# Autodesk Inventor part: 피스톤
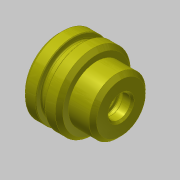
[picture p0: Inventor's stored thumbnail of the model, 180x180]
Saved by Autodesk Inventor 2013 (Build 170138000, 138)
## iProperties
Created: 2020-02
Part Number: 피스톤
Material: 강철, 탄소
Document SubType Name: Modeling
Designer: mduedu
Density: 1 g/cm^3
Author: mduedu
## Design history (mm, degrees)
sketch "스케치1"
  geometry: L1 (0, 0)-(20, 0); L2 (20, 0)-(20, 20); L3 (20, 20)-(0, 20); L4 (0, 20)-(0, 0); L5 (20, 0)-(33, 0); L6 (33, 0)-(33, 15); L7 (33, 15)-(20, 15); L8 (20, 15)-(20, 0)
  constraints: 16 end point, 4 parallel, 2 horizontal, 2 perpendicular
  dimensions: "d0" = 33 distance between parallel lines of L6 L4; "d2" = 20 distance of L2.end L3.end; "d3" = 40 diameter of L3 L1; "d4" = 30 diameter of L7 L5
revolve "회전1" sketch "스케치1" stored, may be unused: angle "d5" = 90 deg
sketch "스케치2"
  geometry: L1 (0, -20)-(0, 20) reference; L2 (0, 20)-(20, 20) reference; L3 (20, 20)-(20, 15) reference; L4 (20, 15)-(33, 15) reference; L5 (33, 15)-(33, -15) reference; L6 (33, -15)-(20, -15) reference; L7 (20, -15)-(20, -20) reference; L8 (20, -20)-(0, -20) reference; L9 (0, 0)-(20, 0); L10 (20, 0)-(20, 11); L11 (20, 11)-(0, 11); L12 (0, 11)-(0, 0); L13 (33, 0)-(20, 0); L14 (20, 0)-(20, 6); L15 (20, 6)-(33, 6); L16 (33, 6)-(33, 0)
  constraints: 16 end point, 4 parallel, 2 horizontal, 2 perpendicular, 1 midpoint, 1 point on line
  dimensions: "d6" = 22 diameter of L11 L9; "d8" = 12 diameter of L15 L13; "d9" = 20 distance of L10.end L11.end
revolve "회전2" sketch "스케치2" stored, may be unused: angle "d10" = 90 deg
chamfer "모따기1" distance "d11" = 2; stored, may be unused: second distance "d12" = 2, angle "d13" = 45 deg
sketch "스케치3"
  geometry: L1 (20, -11)-(20, -6) reference; L2 (20, -6)-(33, -6) reference; L3 (33, -6)-(33, -13) reference; L4 (33, -13)-(31, -15) reference; L5 (31, -15)-(20, -15) reference; L6 (20, -15)-(20, -18) reference; L7 (20, -18)-(18, -20) reference; L8 (18, -20)-(2, -20) reference; L9 (2, -20)-(0, -18) reference; L10 (0, -18)-(0, -11) reference; L11 (0, -11)-(20, -11) reference; L12 (20, 6)-(20, 11) reference; L13 (20, 11)-(0, 11) reference; L14 (0, 11)-(0, 18) reference; L15 (0, 18)-(2, 20) reference; L16 (2, 20)-(18, 20) reference; L17 (18, 20)-(20, 18) reference; L18 (20, 18)-(20, 15) reference; L19 (20, 15)-(31, 15) reference; L20 (31, 15)-(33, 13) reference; L21 (33, 13)-(33, 6) reference; L22 (33, 6)-(20, 6) reference; L23 (7.65, 20)-(12.35, 20); L24 (12.35, 20)-(12.35, 17); L25 (12.35, 17)-(7.65, 17); L26 (7.65, 17)-(7.65, 20); L27 (24.4, 6)-(27.6, 6); L28 (27.6, 6)-(27.6, 8); L29 (27.6, 8)-(24.4, 8); L30 (24.4, 8)-(24.4, 6); L31 (10, 17)-(10, 20); L32 (26, 6)-(26, 8); L33 (-6.6, 0)-(39.6, 0) reference; 1 further point
  constraints: 20 end point, 4 midpoint, 4 parallel, 2 horizontal, 2 perpendicular, 2 point on line
  dimensions: "d14" = 10 distance between parallel lines of L31 L14; "d15" = 7 distance between parallel lines of L32 L21; "d16" = 4.7 distance between parallel lines of L24 L26; "d17" = 34 diameter of L25 L33; "d18" = 16 diameter of L29 L33; "d19" = 3.2 distance of L28.end L29.end
revolve "회전3" sketch "스케치3" stored, may be unused: angle "d20" = 90 deg
fillet "모깎기1" dims "d21" = 0.8
fillet "모깎기2" dims "d22" = 0.4
chamfer "모따기2" distance "d23" = 0.3; stored, may be unused: second distance "d24" = 2, angle "d25" = 45 deg
chamfer "모따기3" distance "d26" = 0.3; stored, may be unused: second distance "d27" = 2, angle "d28" = 45 deg
chamfer "모따기4" distance "d29" = 1; stored, may be unused: second distance "d30" = 2, angle "d31" = 45 deg
node "솔리드1"
node "절단 모서리 투영1"
node "절단 모서리 투영2"
